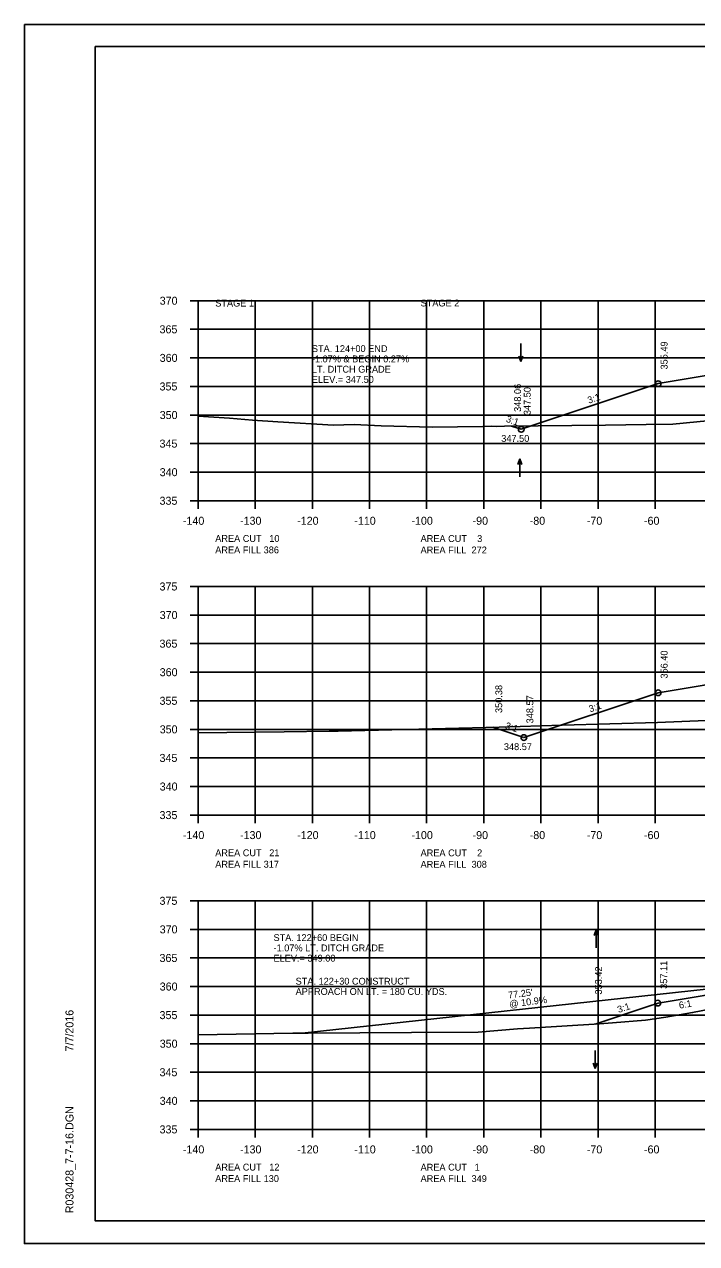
# Model space of a CAD drawing. Extents: x 1374859 to 1376773, y 382242 to 389804.
# Drawn here: x 1375964.2 to 1376081.8, y 384375.1 to 384588.5 of the extents above; entities that cross this region are included whole.
import ezdxf

# ---------------------------------------------------------------- set-up
doc = ezdxf.new("R2010")
doc.units = 0
for name, color, linetype in [('R_Axis', 7, 'Continuous'), ('R_Axis Annot', 7, 'Continuous'), ('R_Border', 7, 'Continuous'), ('R_Detour Annot', 7, 'Continuous'), ('R_Drive', 7, 'Continuous'), ('R_Exist Surface', 7, 'Continuous'), ('R_Fin Surface', 7, 'Continuous'), ('R_Grid', 7, 'Continuous'), ('R_No Plot', 7, 'Continuous'), ('R_Water Annot', 7, 'Continuous'), ('R_Xsect Elev', 7, 'Continuous'), ('R_Xsect Slope', 7, 'Continuous')]:
    doc.layers.add(name, color=color, linetype=linetype)

msp = doc.modelspace()

# ---------------------------------------------------------------- linework, layer by layer
at = {"layer": 'R_Axis'}
for p, q in [((1375993.17, 384540.1), (1375994.57, 384540.1)), ((1375994.57, 384505.1), (1375994.57, 384540.1)), ((1375993.17, 384535.1), (1375994.57, 384535.1)), ((1375993.17, 384530.1), (1375994.57, 384530.1)), ((1375993.17, 384525.1), (1375994.57, 384525.1)), ((1375993.17, 384520.1), (1375994.57, 384520.1)), ((1375993.17, 384515.1), (1375994.57, 384515.1)), ((1375993.17, 384510.1), (1375994.57, 384510.1)), ((1375993.17, 384505.1), (1375994.57, 384505.1)), ((1375994.57, 384505.1), (1376274.57, 384505.1)), ((1375994.57, 384503.7), (1375994.57, 384505.1)), ((1376004.57, 384503.7), (1376004.57, 384505.1)), ((1376014.57, 384503.7), (1376014.57, 384505.1)), ((1376024.57, 384503.7), (1376024.57, 384505.1)), ((1376034.57, 384503.7), (1376034.57, 384505.1)), ((1376044.57, 384503.7), (1376044.57, 384505.1)), ((1376054.57, 384503.7), (1376054.57, 384505.1)), ((1376064.57, 384503.7), (1376064.57, 384505.1)), ((1376074.57, 384503.7), (1376074.57, 384505.1)), ((1375993.17, 384490.1), (1375994.57, 384490.1)), ((1375994.57, 384450.1), (1375994.57, 384490.1)), ((1375993.17, 384485.1), (1375994.57, 384485.1)), ((1375993.17, 384480.1), (1375994.57, 384480.1)), ((1375993.17, 384475.1), (1375994.57, 384475.1)), ((1375993.17, 384470.1), (1375994.57, 384470.1)), ((1375993.17, 384465.1), (1375994.57, 384465.1)), ((1375993.17, 384460.1), (1375994.57, 384460.1)), ((1375993.17, 384455.1), (1375994.57, 384455.1)), ((1375993.17, 384450.1), (1375994.57, 384450.1)), ((1375994.57, 384450.1), (1376274.57, 384450.1)), ((1375994.57, 384448.7), (1375994.57, 384450.1)), ((1376004.57, 384448.7), (1376004.57, 384450.1)), ((1376014.57, 384448.7), (1376014.57, 384450.1)), ((1376024.57, 384448.7), (1376024.57, 384450.1)), ((1376034.57, 384448.7), (1376034.57, 384450.1)), ((1376044.57, 384448.7), (1376044.57, 384450.1)), ((1376054.57, 384448.7), (1376054.57, 384450.1)), ((1376064.57, 384448.7), (1376064.57, 384450.1)), ((1376074.57, 384448.7), (1376074.57, 384450.1)), ((1375993.17, 384435.1), (1375994.57, 384435.1)), ((1375994.57, 384395.1), (1375994.57, 384435.1)), ((1375993.17, 384430.1), (1375994.57, 384430.1)), ((1375993.17, 384425.1), (1375994.57, 384425.1)), ((1375993.17, 384420.1), (1375994.57, 384420.1)), ((1375993.17, 384415.1), (1375994.57, 384415.1)), ((1375993.17, 384410.1), (1375994.57, 384410.1)), ((1375993.17, 384405.1), (1375994.57, 384405.1)), ((1375993.17, 384400.1), (1375994.57, 384400.1)), ((1375993.17, 384395.1), (1375994.57, 384395.1)), ((1375994.57, 384395.1), (1376274.57, 384395.1)), ((1375994.57, 384393.7), (1375994.57, 384395.1)), ((1376004.57, 384393.7), (1376004.57, 384395.1)), ((1376014.57, 384393.7), (1376014.57, 384395.1)), ((1376024.57, 384393.7), (1376024.57, 384395.1)), ((1376034.57, 384393.7), (1376034.57, 384395.1)), ((1376044.57, 384393.7), (1376044.57, 384395.1)), ((1376054.57, 384393.7), (1376054.57, 384395.1)), ((1376064.57, 384393.7), (1376064.57, 384395.1)), ((1376074.57, 384393.7), (1376074.57, 384395.1))]:
    msp.add_line(p, q, dxfattribs=at)
at = {"layer": 'R_Border'}
for p, q in [((1375976.57, 384584.56), (1376292.75, 384584.56)), ((1375976.57, 384379.1), (1375976.57, 384584.56)), ((1375976.57, 384379.1), (1375976.57, 384379.1)), ((1376292.75, 384379.1), (1375976.57, 384379.1))]:
    msp.add_line(p, q, dxfattribs=at)
at = {"layer": 'R_Drive'}
msp.add_line((1376012.81, 384411.93), (1376090.1, 384420.34), dxfattribs=at)
at = {"layer": 'R_Exist Surface'}
for points in [[(1375994.57, 384519.88), (1375996.37, 384519.81), (1376000.04, 384519.57), (1376004.12, 384519.23), (1376008.51, 384518.89), (1376018.29, 384518.32), (1376021.88, 384518.42), (1376026.59, 384518.2), (1376035.51, 384517.97), (1376044.39, 384518.07), (1376045.99, 384518.13), (1376046.75, 384518.12), (1376048.22, 384518.15), (1376065.9, 384518.34), (1376072.98, 384518.47), (1376077.65, 384518.51), (1376087.88, 384519.49)], [(1375994.57, 384464.47), (1376009.64, 384464.65), (1376017.53, 384464.78), (1376019.08, 384464.81), (1376047.24, 384465.51), (1376058.31, 384465.81), (1376074.95, 384466.32), (1376092.04, 384467.02), (1376094.54, 384467.14), (1376096.78, 384467.5), (1376097.99, 384467.49)], [(1375994.57, 384411.65), (1376011.15, 384411.94), (1376013.81, 384411.95), (1376031.9, 384412.05), (1376043.6, 384412.12), (1376050.5, 384412.67), (1376052.55, 384412.82), (1376064.82, 384413.58), (1376067.11, 384413.74), (1376072.86, 384414.23), (1376076.42, 384414.74), (1376081.11, 384415.55), (1376087.18, 384416.72)]]:
    msp.add_lwpolyline(points, dxfattribs=at)
at = {"layer": 'R_Fin Surface'}
for points in [[(1376049.43, 384518.16), (1376051.13, 384517.6), (1376075.09, 384525.59), (1376083.13, 384526.93), (1376097.09, 384529.25), (1376105.09, 384529.87), (1376134.59, 384532.14), (1376164.09, 384534.41), (1376172.09, 384535.03), (1376185.9, 384532.73), (1376194.09, 384531.36), (1376225.13, 384521.01)], [(1376046.15, 384465.48), (1376051.59, 384463.67), (1376075.09, 384471.5), (1376083.13, 384472.85), (1376097.09, 384475.17), (1376105.09, 384475.79), (1376134.59, 384478.06), (1376164.09, 384480.33), (1376172.09, 384480.95), (1376185.9, 384478.64), (1376194.09, 384477.28), (1376228.04, 384465.96)], [(1376064.09, 384413.54), (1376073.29, 384416.61), (1376075.08, 384417.21), (1376081.72, 384418.31), (1376083.13, 384418.55), (1376094.64, 384420.47), (1376097.08, 384420.87), (1376103.69, 384421.38), (1376105.08, 384421.49), (1376110.14, 384421.88), (1376134.58, 384423.76), (1376158.89, 384425.63), (1376164.08, 384426.03), (1376165.47, 384426.14), (1376172.08, 384426.65), (1376183.48, 384424.75), (1376185.9, 384424.35), (1376192.66, 384423.22), (1376194.08, 384422.98), (1376200.51, 384420.84), (1376231.7, 384410.44)]]:
    msp.add_lwpolyline(points, dxfattribs=at)
at = {"layer": 'R_Grid'}
for p, q in [((1375994.57, 384540.1), (1376274.57, 384540.1)), ((1375994.57, 384505.1), (1375994.57, 384540.1)), ((1376004.57, 384505.1), (1376004.57, 384540.1)), ((1376014.57, 384505.1), (1376014.57, 384540.1)), ((1376024.57, 384505.1), (1376024.57, 384540.1)), ((1376034.57, 384505.1), (1376034.57, 384540.1)), ((1376044.57, 384505.1), (1376044.57, 384540.1)), ((1376054.57, 384505.1), (1376054.57, 384540.1)), ((1376064.57, 384505.1), (1376064.57, 384540.1)), ((1376074.57, 384505.1), (1376074.57, 384540.1)), ((1375994.57, 384535.1), (1376274.57, 384535.1)), ((1375994.57, 384530.1), (1376274.57, 384530.1)), ((1375994.57, 384525.1), (1376274.57, 384525.1)), ((1375994.57, 384520.1), (1376274.57, 384520.1)), ((1375994.57, 384515.1), (1376274.57, 384515.1)), ((1375994.57, 384510.1), (1376274.57, 384510.1)), ((1375994.57, 384505.1), (1376274.57, 384505.1)), ((1375994.57, 384490.1), (1376274.57, 384490.1)), ((1375994.57, 384450.1), (1375994.57, 384490.1)), ((1376004.57, 384450.1), (1376004.57, 384490.1)), ((1376014.57, 384450.1), (1376014.57, 384490.1)), ((1376024.57, 384450.1), (1376024.57, 384490.1)), ((1376034.57, 384450.1), (1376034.57, 384490.1)), ((1376044.57, 384450.1), (1376044.57, 384490.1)), ((1376054.57, 384450.1), (1376054.57, 384490.1)), ((1376064.57, 384450.1), (1376064.57, 384490.1)), ((1376074.57, 384450.1), (1376074.57, 384490.1)), ((1375994.57, 384485.1), (1376274.57, 384485.1)), ((1375994.57, 384480.1), (1376274.57, 384480.1)), ((1375994.57, 384475.1), (1376274.57, 384475.1)), ((1375994.57, 384470.1), (1376274.57, 384470.1)), ((1375994.57, 384465.1), (1376274.57, 384465.1)), ((1375994.57, 384460.1), (1376274.57, 384460.1)), ((1375994.57, 384455.1), (1376274.57, 384455.1)), ((1375994.57, 384450.1), (1376274.57, 384450.1)), ((1375994.57, 384435.1), (1376274.57, 384435.1)), ((1375994.57, 384395.1), (1375994.57, 384435.1)), ((1376004.57, 384395.1), (1376004.57, 384435.1)), ((1376014.57, 384395.1), (1376014.57, 384435.1)), ((1376024.57, 384395.1), (1376024.57, 384435.1)), ((1376034.57, 384395.1), (1376034.57, 384435.1)), ((1376044.57, 384395.1), (1376044.57, 384435.1)), ((1376054.57, 384395.1), (1376054.57, 384435.1)), ((1376064.57, 384395.1), (1376064.57, 384435.1)), ((1376074.57, 384395.1), (1376074.57, 384435.1)), ((1375994.57, 384430.1), (1376274.57, 384430.1)), ((1375994.57, 384425.1), (1376274.57, 384425.1)), ((1375994.57, 384420.1), (1376274.57, 384420.1)), ((1375994.57, 384415.1), (1376274.57, 384415.1)), ((1375994.57, 384410.1), (1376274.57, 384410.1)), ((1375994.57, 384405.1), (1376274.57, 384405.1)), ((1375994.57, 384400.1), (1376274.57, 384400.1)), ((1375994.57, 384395.1), (1376274.57, 384395.1))]:
    msp.add_line(p, q, dxfattribs=at)
at = {"layer": 'R_No Plot'}
for p, q in [((1375964.17, 384588.45), (1376297.5, 384588.45)), ((1375964.17, 384375.12), (1376297.5, 384375.12))]:
    msp.add_line(p, q, dxfattribs=at)
for points in [[(1375964.16, 384588.45), (1376297.5, 384588.45), (1376297.5, 384375.12), (1375964.16, 384375.12)], [(1376210.49, 384584.56), (1376210.49, 384574.68), (1376246.22, 384574.68), (1376246.22, 384571.76), (1376269.42, 384571.76), (1376269.42, 384547.43), (1376292.75, 384547.43), (1376292.75, 384379.1), (1375976.57, 384379.1), (1375976.57, 384584.56)]]:
    msp.add_lwpolyline(points, close=True, dxfattribs=at)
for centre in [(1376075.09, 384525.59), (1376051.13, 384517.6), (1376075.09, 384471.5), (1376051.59, 384463.67), (1376075.02, 384417.21)]:
    msp.add_circle(centre, 0.5, dxfattribs=at)
at = {"layer": 'R_Water Annot'}
for p, q in [((1376051.05, 384532.59), (1376051.05, 384529.44)), ((1376051.05, 384529.44), (1376050.7, 384530.4)), ((1376051.05, 384529.44), (1376051.4, 384530.4)), ((1376050.88, 384512.43), (1376050.53, 384511.47)), ((1376050.88, 384509.29), (1376050.88, 384512.43)), ((1376050.88, 384512.43), (1376051.23, 384511.47)), ((1376064.23, 384430.01), (1376063.88, 384429.05)), ((1376064.23, 384426.87), (1376064.23, 384430.01)), ((1376064.23, 384430.01), (1376064.58, 384429.05)), ((1376064.04, 384408.88), (1376064.04, 384405.74)), ((1376064.04, 384405.74), (1376063.69, 384406.7)), ((1376064.04, 384405.74), (1376064.39, 384406.7))]:
    msp.add_line(p, q, dxfattribs=at)

# ---------------------------------------------------------------- texts
at = {"layer": 'R_Axis Annot'}
for s, height, p in [('370', 1.4, (1375987.85, 384539.4)), ('365', 1.4, (1375987.82, 384534.4)), ('360', 1.4, (1375987.85, 384529.4)), ('355', 1.4, (1375987.82, 384524.4)), ('350', 1.4, (1375987.85, 384519.4)), ('345', 1.4, (1375987.82, 384514.4)), ('340', 1.4, (1375987.85, 384509.4)), ('335', 1.4, (1375987.82, 384504.4)), ('-140', 1.4, (1375991.91, 384500.9)), ('-130', 1.4, (1376001.91, 384500.9)), ('-120', 1.4, (1376011.91, 384500.9)), ('-110', 1.4, (1376021.91, 384500.9)), ('-100', 1.4, (1376031.91, 384500.9)), ('-90', 1.4, (1376042.61, 384500.9)), ('-80', 1.4, (1376052.61, 384500.9)), ('-70', 1.4, (1376062.61, 384500.9)), ('-60', 1.4, (1376072.61, 384500.9)), ('AREA CUT   10', 1.2, (1375997.57, 384497.9)), ('AREA CUT    3', 1.2, (1376033.51, 384497.89)), ('AREA FILL 386', 1.2, (1375997.57, 384495.9)), ('AREA FILL  272', 1.2, (1376033.51, 384495.89)), ('375', 1.4, (1375987.82, 384489.4)), ('370', 1.4, (1375987.85, 384484.4)), ('365', 1.4, (1375987.82, 384479.4)), ('360', 1.4, (1375987.85, 384474.4)), ('355', 1.4, (1375987.82, 384469.4)), ('350', 1.4, (1375987.85, 384464.4)), ('345', 1.4, (1375987.82, 384459.4)), ('340', 1.4, (1375987.85, 384454.4)), ('335', 1.4, (1375987.82, 384449.4)), ('-140', 1.4, (1375991.91, 384445.9)), ('-130', 1.4, (1376001.91, 384445.9)), ('-120', 1.4, (1376011.91, 384445.9)), ('-110', 1.4, (1376021.91, 384445.9)), ('-100', 1.4, (1376031.91, 384445.9)), ('-90', 1.4, (1376042.61, 384445.9)), ('-80', 1.4, (1376052.61, 384445.9)), ('-70', 1.4, (1376062.61, 384445.9)), ('-60', 1.4, (1376072.61, 384445.9)), ('AREA CUT   21', 1.2, (1375997.57, 384442.9)), ('AREA CUT    2', 1.2, (1376033.51, 384442.89)), ('AREA FILL 317', 1.2, (1375997.57, 384440.9)), ('AREA FILL  308', 1.2, (1376033.51, 384440.89)), ('375', 1.4, (1375987.82, 384434.4)), ('370', 1.4, (1375987.85, 384429.4)), ('365', 1.4, (1375987.82, 384424.4)), ('360', 1.4, (1375987.85, 384419.4)), ('355', 1.4, (1375987.82, 384414.4)), ('350', 1.4, (1375987.85, 384409.4)), ('345', 1.4, (1375987.82, 384404.4)), ('340', 1.4, (1375987.85, 384399.4)), ('335', 1.4, (1375987.82, 384394.4)), ('-140', 1.4, (1375991.91, 384390.9)), ('-130', 1.4, (1376001.91, 384390.9)), ('-120', 1.4, (1376011.91, 384390.9)), ('-110', 1.4, (1376021.91, 384390.9)), ('-100', 1.4, (1376031.91, 384390.9)), ('-90', 1.4, (1376042.61, 384390.9)), ('-80', 1.4, (1376052.61, 384390.9)), ('-70', 1.4, (1376062.61, 384390.9)), ('-60', 1.4, (1376072.61, 384390.9)), ('AREA CUT   12', 1.2, (1375997.57, 384387.9)), ('AREA CUT   1', 1.2, (1376033.51, 384387.89)), ('AREA FILL 130', 1.2, (1375997.57, 384385.9)), ('AREA FILL  349', 1.2, (1376033.51, 384385.89))]:
    msp.add_text(s, height=height, dxfattribs=at).set_placement(p)
for s, p in [('STAGE 1', (1375997.57, 384539.08)), ('STAGE 2', (1376033.51, 384539.1))]:
    msp.add_text(s, height=1.2, rotation=360, dxfattribs=at).set_placement(p)
at = {"layer": 'R_Border'}
for s, p in [('7/7/2016', (1375972.76, 384408.74)), ('R030428_7-7-16.DGN', (1375972.76, 384380.42))]:
    msp.add_text(s, height=1.4, rotation=90, dxfattribs=at).set_placement(p)
at = {"layer": 'R_Detour Annot'}
for s, p in [('STA. 124+00 END', (1376014.48, 384531.12)), ('-1.07% & BEGIN 0.27%', (1376014.48, 384529.32)), ('LT. DITCH GRADE', (1376014.48, 384527.52)), ('ELEV.= 347.50', (1376014.48, 384525.72)), ('STA. 122+60 BEGIN', (1376007.77, 384428.06)), ('-1.07% LT. DITCH GRADE', (1376007.77, 384426.26)), ('ELEV.= 349.00', (1376007.77, 384424.46))]:
    msp.add_text(s, height=1.2, dxfattribs=at).set_placement(p)
at = {"layer": 'R_Water Annot'}
for s, p in [('STA. 122+30 CONSTRUCT', (1376011.64, 384420.43)), ('APPROACH ON LT. = 180 CU. YDS.', (1376011.64, 384418.63))]:
    msp.add_text(s, height=1.2, dxfattribs=at).set_placement(p)
at = {"layer": 'R_Xsect Elev'}
for s, p in [('355.49', (1376076.74, 384528.07)), ('348.06', (1376051.09, 384520.65)), ('347.50', (1376052.78, 384520.08)), ('356.40', (1376076.74, 384473.99)), ('350.38', (1376047.8, 384467.96)), ('348.57', (1376053.24, 384466.15)), ('357.11', (1376076.67, 384419.69)), ('353.42', (1376065.25, 384418.7))]:
    msp.add_text(s, height=1.2, rotation=90, dxfattribs=at).set_placement(p)
for s, p in [('347.50', (1376047.63, 384515.4)), ('348.57', (1376048.09, 384461.47))]:
    msp.add_text(s, height=1.2, dxfattribs=at).set_placement(p)
at = {"layer": 'R_Xsect Slope'}
for s, rotation, p in [('3:1', 18.4349, (1376062.95, 384522.07)), ('3:1', 341.5651, (1376048.36, 384518.93)), ('3:1', 18.4349, (1376063.18, 384468.06)), ('3:1', 341.5651, (1376048.21, 384465.27)), ("77.25'", 7.1602, (1376048.91, 384417.99)), ('@ 10.9%', 7.1602, (1376049.11, 384416.41)), ('6:1', 9.4645, (1376078.83, 384416.22)), ('3:1', 18.4347, (1376068.18, 384415.46))]:
    msp.add_text(s, height=1.2, rotation=rotation, dxfattribs=at).set_placement(p)

doc.saveas('drawing.dxf')
